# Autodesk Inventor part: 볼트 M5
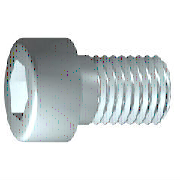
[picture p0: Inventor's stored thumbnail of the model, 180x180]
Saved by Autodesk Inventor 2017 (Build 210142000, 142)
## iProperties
IsCustomPart: 0
Created: 2021-07
Part Number: 볼트 M5
Material: 강철, 연강
Description: 6각머리 태핑 나사
Document SubType Name: Modeling
Standard: KS B 1003
Standards Organization: KS
Language: ko-KR
Size Designation: M 5 x 20
Categories: <MemberInstance><Categories><Category DisplayName="조임쇠" InternalName="e4da775c-781d-43d5-af7c-5136215cf5a6" Mnemonic="FSTN"><Category DisplayName="볼트" InternalN
Density: 7.86 g/cm^3
Mass: 4.9629 g
Surface Area: 5.88237 cm^2
Volume: 0.631412 cm^3
Project: mdu
Appearance: 강철
Author: mdu
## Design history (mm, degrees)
sketch "스케치1"
  geometry: L1 (-1.167, 0)-(20, 0); L2 (20, 0)-(20, 2.5); L3 (20, 2.5)-(2, 2.5); L4 (2, 2.5)-(1.509, 2.5); L5 (1.509, 2.5)-(0, 2.5); L6 (0, 2.5)-(0, 4.25); L7 (0, 4.25)-(-5, 4.25); L8 (-5, 4.25)-(-5, 2.309); L9 (-5, 2.309)-(-2.5, 2.309); L10 (-2.5, 2.309)-(-1.167, 0); L11 (-10, 0)-(25, 0) reference; L12 (0, -0.85)-(0, 5.1) reference; L13 (2, 2.5)-(0, 2.5)
  constraints: 22 end point, 6 parallel, 2 collinear, 2 perpendicular, 1 horizontal, 1 point on line
  dimensions: "d1" = 18 distance from line of L3.end L2 (= GEL); "d2" = 0.49086 distance of L4.end L3.end (computed from GAL); "d3" = 5 distance between parallel lines of L8 L6 (= KOH); "d4" = 2.5 distance of L8.end L9.end (= INTI); "d5" = 60 deg angle of L10 L1; "d6" = 5 diameter of L3 L1 (= GD); "d7" = 5 diameter of L5 L1 (= BDM); "d8" = 4.6188 diameter of L9 L1 (= 1.1547 x SW); "d9" = 8.5 diameter of L7 L1 (= KOD); "d26" = 20 distance between parallel lines of L12 L2 (= NLG)
revolve "본체" sketch "스케치1" stored, may be unused: angle "d10" = 90 deg
sketch "스케치2"
  geometry: L1 (0, -5.95)-(0, 5.95) reference; L2 (-5.95, 0)-(5.95, 0) reference; L3 (2.309, 0)-(1.155, -2); L4 (1.155, -2)-(-1.155, -2); L5 (-1.155, -2)-(-2.309, 0); L6 (-2.309, 0)-(-1.155, 2); L7 (-1.155, 2)-(1.155, 2); L8 (1.155, 2)-(2.309, 0); 2 further points
  constraints: 12 end point, 1 coincident, 1 horizontal alignment, 1 point on line, 12 other
extrude "슬롯" join sketch "스케치2" stored distance "d11" = 10; taper "d12" = 0 deg
workplane "Work Plane1"
fillet "Fillet2" dims "d30" = 0.1 (= R)
body "Solid1"
fillet "모깎기1" dims "d17" = 0.5 (= RR)
feature "스레드" dims "d13" = 18 (= GEL), "d14" = 0
chamfer "모따기1" distance "d15" = 0.49076 (= -0.5 x SPD + 0.5 x GD); stored, may be unused: second distance "d16" = 0.49076 (= GUL), angle "d27" = 45 deg
other parameters: "GD" = 5 (= NND) [user parameter; used in 2 equation terms], "NLG" = 20 [user parameter; used in 1 equation term], "GEL" = 18 [user parameter; used in 2 equation terms], "KOD" = 8.5 [user parameter; used in 1 equation term], "KOH" = 5 [user parameter; used in 1 equation term], "INTI" = 2.5 [user parameter; used in 1 equation term], "GAL" = 0.49076 (= 0.61345 x PTC) [user parameter; used in 1 equation term], "GUL" = 0.49076 (= 0.61345 x PTC) [user parameter; used in 1 equation term], "BDM" = 5 (= NND) [user parameter; used in 1 equation term], "SW" = 4 [user parameter; used in 2 equation terms], "RR" = 0.5 [user parameter; used in 1 equation term], "SPD" = 4.01848 (= NND - 1.2269 x PTC) [user parameter; used in 1 equation term], "d19" = 0, "d28" = 0, "d29" = 0, "R" = 0.1 [user parameter; used in 1 equation term], "PHH" = 0.2 [user parameter], "GD1" = 4.01848 (= THREADDIA - 1.2269 x PTC) [user parameter], "THREADDIA" = 5 [user parameter; used in 1 equation term], "FAWI" = 45 deg [user parameter], "TPU" = 12.5 (computed from PTC) [user parameter], "PTC" = 0.8 [user parameter; used in 5 equation terms], "NND" = 5 [user parameter; used in 3 equation terms], "TOA" = 30 deg [user parameter], "E0" = 4.62 (= 1.155 x SW) [user parameter]
